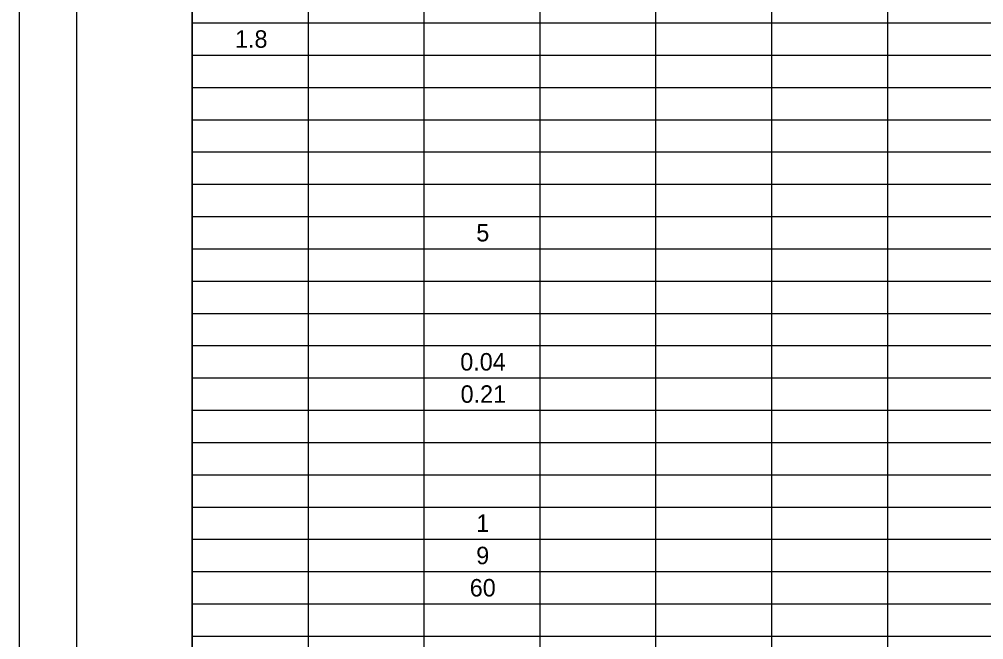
# Model space of a CAD drawing. Extents: x 0 to 34, y 0 to 22.
# Drawn here: x 0 to 8.36, y 11.11 to 16.49 of the extents above; entities that cross this region are included whole.
import ezdxf

# ---------------------------------------------------------------- set-up
doc = ezdxf.new("R2010")
doc.units = 0
for name, color, linetype in [('Default', 7, 'Continuous'), ('SH_Border', 7, 'Continuous'), ('SH_Cut_Line', 7, 'Continuous')]:
    doc.layers.add(name, color=color, linetype=linetype)

msp = doc.modelspace()

# ---------------------------------------------------------------- linework, layer by layer
at = {"layer": 'Default'}
for p, q in [((1.5, 21.5), (1.5, 0.5)), ((2.5047, 20.94), (2.5047, 0.5)), ((3.5094, 20.94), (3.5094, 0.5)), ((4.5141, 20.94), (4.5141, 0.5)), ((5.5188, 20.94), (5.5188, 0.5)), ((6.5235, 20.94), (6.5235, 0.5)), ((7.5282, 20.94), (7.5282, 0.5)), ((1.5, 16.46), (32.0035, 16.46)), ((1.5, 16.18), (32.0035, 16.18)), ((1.5, 15.9), (32.0035, 15.9)), ((1.5, 15.62), (32.0035, 15.62)), ((1.5, 15.34), (32.0035, 15.34)), ((1.5, 15.06), (32.0035, 15.06)), ((1.5, 14.78), (32.0035, 14.78)), ((1.5, 14.5), (32.0035, 14.5)), ((1.5, 14.22), (32.0035, 14.22)), ((1.5, 13.94), (32.0035, 13.94)), ((1.5, 13.66), (32.0035, 13.66)), ((1.5, 13.38), (32.0035, 13.38)), ((1.5, 13.1), (32.0035, 13.1)), ((1.5, 12.82), (32.0035, 12.82)), ((1.5, 12.54), (32.0035, 12.54)), ((1.5, 12.26), (32.0035, 12.26)), ((1.5, 11.98), (32.0035, 11.98)), ((1.5, 11.7), (32.0035, 11.7)), ((1.5, 11.42), (32.0035, 11.42)), ((1.5, 11.14), (32.0035, 11.14))]:
    msp.add_line(p, q, dxfattribs=at)
at = {"layer": 'SH_Border'}
for points in [[(0.5, 21.5), (1.5, 21.5), (1.5, 0.5), (0.5, 0.5)], [(1.5, 21.5), (33.5, 21.5), (33.5, 0.5), (1.5, 0.5)]]:
    msp.add_lwpolyline(points, close=True, dxfattribs=at)
at = {"layer": 'SH_Cut_Line'}
msp.add_lwpolyline([(0, 0), (34, 0), (34, 22), (0, 22)], close=True, dxfattribs=at)

# ---------------------------------------------------------------- texts
at = {"layer": 'Default'}
for s, height, p in [('1.8', 0.15153, (1.8708, 16.2442)), ('5', 0.1515, (3.9636, 14.5642)), ('0.04', 0.15153, (3.8244, 13.4442)), ('0.21', 0.15153, (3.8272, 13.1642)), ('1', 0.1515, (3.9632, 12.0442)), ('9', 0.1515, (3.9628, 11.7642)), ('60', 0.15153, (3.9066, 11.4842))]:
    msp.add_text(s, height=height, dxfattribs=at).set_placement(p)

doc.saveas('drawing.dxf')
